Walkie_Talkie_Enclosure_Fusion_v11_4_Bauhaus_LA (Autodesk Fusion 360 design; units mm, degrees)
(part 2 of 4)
sketch "Restore Quiet Orb Status Aperture Sketch" plane through (0, 0, 0) normal (0, 0, 1) x axis (1, 0, 0)
  line L1 (0.05, -0.2) -> (-0.05, -0.2)
  line L2 (2.2, 8.05) -> (2.2, 1.95)
  line L3 (-0.05, 10.2) -> (0.05, 10.2)
  line L4 (-2.2, 1.95) -> (-2.2, 8.05)
  arc A1 centre (0.05, 1.95) radius 2.15 clockwise from (2.2, 1.95) to (0.05, -0.2)
  arc A2 centre (0.05, 8.05) radius 2.15 clockwise from (0.05, 10.2) to (2.2, 8.05)
  arc A3 centre (-0.05, 8.05) radius 2.15 clockwise from (-2.2, 8.05) to (-0.05, 10.2)
  arc A4 centre (-0.05, 1.95) radius 2.15 clockwise from (-0.05, -0.2) to (-2.2, 1.95)
extrude "Extrude33" cut sketch "Restore Quiet Orb Status Aperture Sketch" blind 3.2
sketch "Microphone Breakout Pocket Sketch" plane through (0, 0, 0) normal (0, 0, 1) x axis (1, 0, 0)
  line L1 (-6.4, -21.2) -> (-21.6, -21.2)
  line L2 (-4.9, -8.3) -> (-4.9, -19.7)
  line L3 (-21.6, -6.8) -> (-6.4, -6.8)
  line L4 (-23.1, -19.7) -> (-23.1, -8.3)
  line L5 (-6.55, -20.6) -> (-21.45, -20.6)
  line L6 (-5.5, -8.45) -> (-5.5, -19.55)
  line L7 (-21.45, -7.4) -> (-6.55, -7.4)
  line L8 (-22.5, -19.55) -> (-22.5, -8.45)
  arc A1 centre (-6.4, -19.7) radius 1.5 clockwise from (-4.9, -19.7) to (-6.4, -21.2)
  arc A2 centre (-6.4, -8.3) radius 1.5 clockwise from (-6.4, -6.8) to (-4.9, -8.3)
  arc A3 centre (-21.6, -8.3) radius 1.5 clockwise from (-23.1, -8.3) to (-21.6, -6.8)
  arc A4 centre (-21.6, -19.7) radius 1.5 clockwise from (-21.6, -21.2) to (-23.1, -19.7)
  arc A5 centre (-6.55, -19.55) radius 1.05 clockwise from (-5.5, -19.55) to (-6.55, -20.6)
  arc A6 centre (-6.55, -8.45) radius 1.05 clockwise from (-6.55, -7.4) to (-5.5, -8.45)
  arc A7 centre (-21.45, -8.45) radius 1.05 clockwise from (-22.5, -8.45) to (-21.45, -7.4)
  arc A8 centre (-21.45, -19.55) radius 1.05 clockwise from (-21.45, -20.6) to (-22.5, -19.55)
extrude "Extrude34" add sketch "Microphone Breakout Pocket Sketch" blind 3.2 from offset 2
sketch "Microphone Snap Lip Sketch" plane through (0, 0, 0) normal (0, 0, 1) x axis (1, 0, 0)
  line L1 (-12.5, -20.9) -> (-15.5, -20.9)
  line L2 (-12, -20.1) -> (-12, -20.4)
  line L3 (-15.5, -19.6) -> (-12.5, -19.6)
  line L4 (-16, -20.4) -> (-16, -20.1)
  arc A1 centre (-12.5, -20.4) radius 0.5 clockwise from (-12, -20.4) to (-12.5, -20.9)
  arc A2 centre (-12.5, -20.1) radius 0.5 clockwise from (-12.5, -19.6) to (-12, -20.1)
  arc A3 centre (-15.5, -20.1) radius 0.5 clockwise from (-16, -20.1) to (-15.5, -19.6)
  arc A4 centre (-15.5, -20.4) radius 0.5 clockwise from (-15.5, -20.9) to (-16, -20.4)
extrude "Extrude35" add sketch "Microphone Snap Lip Sketch" blind 0.4 from offset 4.95
sketch "Microphone Snap Lip Sketch (1)" plane through (0, 0, 0) normal (0, 0, 1) x axis (1, 0, 0)
  line L1 (-12.5, -8.4) -> (-15.5, -8.4)
  line L2 (-12, -7.6) -> (-12, -7.9)
  line L3 (-15.5, -7.1) -> (-12.5, -7.1)
  line L4 (-16, -7.9) -> (-16, -7.6)
  arc A1 centre (-12.5, -7.9) radius 0.5 clockwise from (-12, -7.9) to (-12.5, -8.4)
  arc A2 centre (-12.5, -7.6) radius 0.5 clockwise from (-12.5, -7.1) to (-12, -7.6)
  arc A3 centre (-15.5, -7.6) radius 0.5 clockwise from (-16, -7.6) to (-15.5, -7.1)
  arc A4 centre (-15.5, -7.9) radius 0.5 clockwise from (-15.5, -8.4) to (-16, -7.9)
extrude "Extrude36" add sketch "Microphone Snap Lip Sketch (1)" blind 0.4 from offset 4.95
sketch "Front Switch Clamp Boss Sketch" plane through (0, 0, 0) normal (0, 0, 1) x axis (1, 0, 0)
  circle C1 centre (-17, -47) radius 2.1
extrude "Extrude37" add sketch "Front Switch Clamp Boss Sketch" blind 8.85 from offset 2
sketch "Front Switch Clamp M2 Pilot Sketch" plane through (0, 0, 0) normal (0, 0, 1) x axis (1, 0, 0)
  circle C1 centre (-17, -47) radius 0.85
extrude "Extrude38" cut sketch "Front Switch Clamp M2 Pilot Sketch" blind 8.4 from offset 2.6
sketch "Front Switch Clamp Boss Sketch (1)" plane through (0, 0, 0) normal (0, 0, 1) x axis (1, 0, 0)
  circle C1 centre (17, -47) radius 2.1
extrude "Extrude39" add sketch "Front Switch Clamp Boss Sketch (1)" blind 8.85 from offset 2
sketch "Front Switch Clamp M2 Pilot Sketch (1)" plane through (0, 0, 0) normal (0, 0, 1) x axis (1, 0, 0)
  circle C1 centre (17, -47) radius 0.85
extrude "Extrude40" cut sketch "Front Switch Clamp M2 Pilot Sketch (1)" blind 8.4 from offset 2.6
sketch "Front Switch Body Reaction Bridge Sketch" plane through (0, 0, 0) normal (0, 0, 1) x axis (1, 0, 0)
  line L1 (16.5, -55) -> (-16.5, -55)
  line L2 (19.5, -42) -> (19.5, -52)
  line L3 (-16.5, -39) -> (16.5, -39)
  line L4 (-19.5, -52) -> (-19.5, -42)
  line L5 (2, -51) -> (-2, -51)
  line L6 (4, -45) -> (4, -49)
  line L7 (-2, -43) -> (2, -43)
  line L8 (-4, -49) -> (-4, -45)
  arc A1 centre (16.5, -52) radius 3 clockwise from (19.5, -52) to (16.5, -55)
  arc A2 centre (16.5, -42) radius 3 clockwise from (16.5, -39) to (19.5, -42)
  arc A3 centre (-16.5, -42) radius 3 clockwise from (-19.5, -42) to (-16.5, -39)
  arc A4 centre (-16.5, -52) radius 3 clockwise from (-16.5, -55) to (-19.5, -52)
  arc A5 centre (2, -49) radius 2 clockwise from (4, -49) to (2, -51)
  arc A6 centre (2, -45) radius 2 clockwise from (2, -43) to (4, -45)
  arc A7 centre (-2, -45) radius 2 clockwise from (-4, -45) to (-2, -43)
  arc A8 centre (-2, -49) radius 2 clockwise from (-2, -51) to (-4, -49)
extrude "Extrude41" add sketch "Front Switch Body Reaction Bridge Sketch" blind 0.2 from offset 3.2
sketch "PTT Interaction Field Sketch" plane through (0, 0, 0) normal (1, 0, 0) x axis (0, 0, -1)
  line L1 (-14.65, -17.5) -> (-14.85, -17.5)
  line L2 (-7.85, 34.7) -> (-7.85, -10.7)
  line L3 (-14.85, 41.5) -> (-14.65, 41.5)
  line L4 (-21.65, -10.7) -> (-21.65, 34.7)
  arc A1 centre (-14.65, -10.7) radius 6.8 clockwise from (-7.85, -10.7) to (-14.65, -17.5)
  arc A2 centre (-14.65, 34.7) radius 6.8 clockwise from (-14.65, 41.5) to (-7.85, 34.7)
  arc A3 centre (-14.85, 34.7) radius 6.8 clockwise from (-21.65, 34.7) to (-14.85, 41.5)
  arc A4 centre (-14.85, -10.7) radius 6.8 clockwise from (-14.85, -17.5) to (-21.65, -10.7)
extrude "Extrude42" cut sketch "PTT Interaction Field Sketch" blind -0.42 (= "-( 0.42 mm )") from offset 39.2
sketch "Unified Volume Interaction Field Sketch" plane through (0, 0, 0) normal (1, 0, 0) x axis (0, 0, -1)
  line L1 (-14.65, -21.25) -> (-14.85, -21.25)
  line L2 (-7.85, 31.45) -> (-7.85, -14.45)
  line L3 (-14.85, 38.25) -> (-14.65, 38.25)
  line L4 (-21.65, -14.45) -> (-21.65, 31.45)
  arc A1 centre (-14.65, -14.45) radius 6.8 clockwise from (-7.85, -14.45) to (-14.65, -21.25)
  arc A2 centre (-14.65, 31.45) radius 6.8 clockwise from (-14.65, 38.25) to (-7.85, 31.45)
  arc A3 centre (-14.85, 31.45) radius 6.8 clockwise from (-21.65, 31.45) to (-14.85, 38.25)
  arc A4 centre (-14.85, -14.45) radius 6.8 clockwise from (-14.85, -21.25) to (-21.65, -14.45)
extrude "Extrude43" cut sketch "Unified Volume Interaction Field Sketch" blind 0.42 from offset -39.2
sketch "Left PTT Through Opening Sketch" plane through (0, 0, 0) normal (1, 0, 0) x axis (0, 0, -1)
  line L1 (-14.65, -13.2) -> (-14.85, -13.2)
  line L2 (-10.25, 32.8) -> (-10.25, -8.8)
  line L3 (-14.85, 37.2) -> (-14.65, 37.2)
  line L4 (-19.25, -8.8) -> (-19.25, 32.8)
  arc A1 centre (-14.65, -8.8) radius 4.4 clockwise from (-10.25, -8.8) to (-14.65, -13.2)
  arc A2 centre (-14.65, 32.8) radius 4.4 clockwise from (-14.65, 37.2) to (-10.25, 32.8)
  arc A3 centre (-14.85, 32.8) radius 4.4 clockwise from (-19.25, 32.8) to (-14.85, 37.2)
  arc A4 centre (-14.85, -8.8) radius 4.4 clockwise from (-14.85, -13.2) to (-19.25, -8.8)
extrude "Extrude44" cut sketch "Left PTT Through Opening Sketch" blind 40
sketch "Volume Up Through Opening Sketch" plane through (0, 0, 0) normal (1, 0, 0) x axis (0, 0, -1)
  line L1 (-14.65, 15.15) -> (-14.85, 15.15)
  line L2 (-10.55, 26.75) -> (-10.55, 19.25)
  line L3 (-14.85, 30.85) -> (-14.65, 30.85)
  line L4 (-18.95, 19.25) -> (-18.95, 26.75)
  arc A1 centre (-14.65, 19.25) radius 4.1 clockwise from (-10.55, 19.25) to (-14.65, 15.15)
  arc A2 centre (-14.65, 26.75) radius 4.1 clockwise from (-14.65, 30.85) to (-10.55, 26.75)
  arc A3 centre (-14.85, 26.75) radius 4.1 clockwise from (-18.95, 26.75) to (-14.85, 30.85)
  arc A4 centre (-14.85, 19.25) radius 4.1 clockwise from (-14.85, 15.15) to (-18.95, 19.25)
extrude "Extrude45" cut sketch "Volume Up Through Opening Sketch" blind -40 (= "-( 40.00 mm )")
sketch "Volume Down Through Opening Sketch" plane through (0, 0, 0) normal (1, 0, 0) x axis (0, 0, -1)
  line L1 (-14.65, -13.85) -> (-14.85, -13.85)
  line L2 (-10.55, -2.25) -> (-10.55, -9.75)
  line L3 (-14.85, 1.85) -> (-14.65, 1.85)
  line L4 (-18.95, -9.75) -> (-18.95, -2.25)
  arc A1 centre (-14.65, -9.75) radius 4.1 clockwise from (-10.55, -9.75) to (-14.65, -13.85)
  arc A2 centre (-14.65, -2.25) radius 4.1 clockwise from (-14.65, 1.85) to (-10.55, -2.25)
  arc A3 centre (-14.85, -2.25) radius 4.1 clockwise from (-18.95, -2.25) to (-14.85, 1.85)
  arc A4 centre (-14.85, -9.75) radius 4.1 clockwise from (-14.85, -13.85) to (-18.95, -9.75)
extrude "Extrude46" cut sketch "Volume Down Through Opening Sketch" blind -40 (= "-( 40.00 mm )")
sketch "USB-C Full-Seating Local Wall Recess Sketch" plane through (0, 0, 0) normal (1, 0, 0) x axis (0, 0, -1)
  line L1 (-12.4264, -27.6393) -> (-12.9264, -27.6393)
  line L2 (-8.9764, -17.8393) -> (-8.9764, -24.1893)
  line L3 (-12.9264, -14.3893) -> (-12.4264, -14.3893)
  line L4 (-16.3764, -24.1893) -> (-16.3764, -17.8393)
  arc A1 centre (-12.4264, -24.1893) radius 3.45 clockwise from (-8.9764, -24.1893) to (-12.4264, -27.6393)
  arc A2 centre (-12.4264, -17.8393) radius 3.45 clockwise from (-12.4264, -14.3893) to (-8.9764, -17.8393)
  arc A3 centre (-12.9264, -17.8393) radius 3.45 clockwise from (-16.3764, -17.8393) to (-12.9264, -14.3893)
  arc A4 centre (-12.9264, -24.1893) radius 3.45 clockwise from (-12.9264, -27.6393) to (-16.3764, -24.1893)
extrude "Extrude47" cut sketch "USB-C Full-Seating Local Wall Recess Sketch" blind -2.9527 (= "-( 2.952733 mm )") from offset 39.2
sketch "Sketch48" plane through (0, 0, 0) normal (1, 0, 0) x axis (0, 0, -1)
  line L1 (-12.6264, -25.7043) -> (-12.7264, -25.7043)
  line L2 (-10.2799, -18.6708) -> (-10.2799, -23.3578)
  line L3 (-12.7264, -16.3243) -> (-12.6264, -16.3243)
  line L4 (-15.0729, -23.3578) -> (-15.0729, -18.6708)
  arc A1 centre (-12.6264, -23.3578) radius 2.3465 clockwise from (-10.2799, -23.3578) to (-12.6264, -25.7043)
  arc A2 centre (-12.6264, -18.6708) radius 2.3465 clockwise from (-12.6264, -16.3243) to (-10.2799, -18.6708)
  arc A3 centre (-12.7264, -18.6708) radius 2.3465 clockwise from (-15.0729, -18.6708) to (-12.7264, -16.3243)
  arc A4 centre (-12.7264, -23.3578) radius 2.3465 clockwise from (-12.7264, -25.7043) to (-15.0729, -23.3578)
extrude "Extrude48" cut sketch "Sketch48" blind 40
sketch "PTT Internal Switch Body Clearance Sketch" plane through (0, 0, 0) normal (1, 0, 0) x axis (0, 0, -1)
  line L1 (-10, 6.65) -> (-19.5, 6.65)
  line L2 (-9.55, 16.9) -> (-9.55, 7.1)
  line L3 (-19.5, 17.35) -> (-10, 17.35)
  line L4 (-19.95, 7.1) -> (-19.95, 16.9)
  arc A1 centre (-10, 7.1) radius 0.45 clockwise from (-9.55, 7.1) to (-10, 6.65)
  arc A2 centre (-10, 16.9) radius 0.45 clockwise from (-10, 17.35) to (-9.55, 16.9)
  arc A3 centre (-19.5, 16.9) radius 0.45 clockwise from (-19.95, 16.9) to (-19.5, 17.35)
  arc A4 centre (-19.5, 7.1) radius 0.45 clockwise from (-19.5, 6.65) to (-19.95, 7.1)
extrude "Extrude49" cut sketch "PTT Internal Switch Body Clearance Sketch" blind 5.1 from offset 31.9
sketch "PTT Switch Cage Anchor Sketch" plane through (0, 0, 0) normal (0, 0, 1) x axis (1, 0, 0)
  line L1 (32, 6.45) -> (31.5, 6.45)
  line L2 (32.35, 7.3) -> (32.35, 6.8)
  line L3 (31.5, 7.65) -> (32, 7.65)
  line L4 (31.15, 6.8) -> (31.15, 7.3)
  arc A1 centre (32, 6.8) radius 0.35 clockwise from (32.35, 6.8) to (32, 6.45)
  arc A2 centre (32, 7.3) radius 0.35 clockwise from (32, 7.65) to (32.35, 7.3)
  arc A3 centre (31.5, 7.3) radius 0.35 clockwise from (31.15, 7.3) to (31.5, 7.65)
  arc A4 centre (31.5, 6.8) radius 0.35 clockwise from (31.5, 6.45) to (31.15, 6.8)
extrude "Extrude50" add sketch "PTT Switch Cage Anchor Sketch" blind 7.35 from offset 2
sketch "PTT Switch Cage Anchor Sketch (1)" plane through (0, 0, 0) normal (0, 0, 1) x axis (1, 0, 0)
  line L1 (32, 16.35) -> (31.5, 16.35)
  line L2 (32.35, 17.2) -> (32.35, 16.7)
  line L3 (31.5, 17.55) -> (32, 17.55)
  line L4 (31.15, 16.7) -> (31.15, 17.2)
  arc A1 centre (32, 16.7) radius 0.35 clockwise from (32.35, 16.7) to (32, 16.35)
  arc A2 centre (32, 17.2) radius 0.35 clockwise from (32, 17.55) to (32.35, 17.2)
  arc A3 centre (31.5, 17.2) radius 0.35 clockwise from (31.15, 17.2) to (31.5, 17.55)
  arc A4 centre (31.5, 16.7) radius 0.35 clockwise from (31.5, 16.35) to (31.15, 16.7)
extrude "Extrude51" add sketch "PTT Switch Cage Anchor Sketch (1)" blind 7.35 from offset 2
sketch "PTT Switch Floor Sketch" plane through (0, 0, 0) normal (0, 0, 1) x axis (1, 0, 0)
  line L1 (36.45, 6.65) -> (31.75, 6.65)
  line L2 (36.9, 16.9) -> (36.9, 7.1)
  line L3 (31.75, 17.35) -> (36.45, 17.35)
  line L4 (31.3, 7.1) -> (31.3, 16.9)
  arc A1 centre (36.45, 7.1) radius 0.45 clockwise from (36.9, 7.1) to (36.45, 6.65)
  arc A2 centre (36.45, 16.9) radius 0.45 clockwise from (36.45, 17.35) to (36.9, 16.9)
  arc A3 centre (31.75, 16.9) radius 0.45 clockwise from (31.3, 16.9) to (31.75, 17.35)
  arc A4 centre (31.75, 7.1) radius 0.45 clockwise from (31.75, 6.65) to (31.3, 7.1)
extrude "Extrude52" add sketch "PTT Switch Floor Sketch" blind 0.55 from offset 9.25
sketch "PTT Switch Inward Backstop Sketch" plane through (0, 0, 0) normal (0, 0, 1) x axis (1, 0, 0)
  line L1 (31.85, 6.65) -> (31.65, 6.65)
  line L2 (32.2, 17) -> (32.2, 7)
  line L3 (31.65, 17.35) -> (31.85, 17.35)
  line L4 (31.3, 7) -> (31.3, 17)
  arc A1 centre (31.85, 7) radius 0.35 clockwise from (32.2, 7) to (31.85, 6.65)
  arc A2 centre (31.85, 17) radius 0.35 clockwise from (31.85, 17.35) to (32.2, 17)
  arc A3 centre (31.65, 17) radius 0.35 clockwise from (31.3, 17) to (31.65, 17.35)
  arc A4 centre (31.65, 7) radius 0.35 clockwise from (31.65, 6.65) to (31.3, 7)
extrude "Extrude53" add sketch "PTT Switch Inward Backstop Sketch" blind 5.75 from offset 9.25
sketch "PTT Switch Side Rail Sketch" plane through (0, 0, 0) normal (0, 0, 1) x axis (1, 0, 0)
  line L1 (36.675, 6.65) -> (32.325, 6.65)
  line L2 (36.975, 7.15) -> (36.975, 6.95)
  line L3 (32.325, 7.45) -> (36.675, 7.45)
  line L4 (32.025, 6.95) -> (32.025, 7.15)
  arc A1 centre (36.675, 6.95) radius 0.3 clockwise from (36.975, 6.95) to (36.675, 6.65)
  arc A2 centre (36.675, 7.15) radius 0.3 clockwise from (36.675, 7.45) to (36.975, 7.15)
  arc A3 centre (32.325, 7.15) radius 0.3 clockwise from (32.025, 7.15) to (32.325, 7.45)
  arc A4 centre (32.325, 6.95) radius 0.3 clockwise from (32.325, 6.65) to (32.025, 6.95)
extrude "Extrude54" add sketch "PTT Switch Side Rail Sketch" blind 5.75 from offset 9.25
sketch "PTT Switch Side Rail Sketch (1)" plane through (0, 0, 0) normal (0, 0, 1) x axis (1, 0, 0)
  line L1 (36.675, 16.55) -> (32.325, 16.55)
  line L2 (36.975, 17.05) -> (36.975, 16.85)
  line L3 (32.325, 17.35) -> (36.675, 17.35)
  line L4 (32.025, 16.85) -> (32.025, 17.05)
  arc A1 centre (36.675, 16.85) radius 0.3 clockwise from (36.975, 16.85) to (36.675, 16.55)
  arc A2 centre (36.675, 17.05) radius 0.3 clockwise from (36.675, 17.35) to (36.975, 17.05)
  arc A3 centre (32.325, 17.05) radius 0.3 clockwise from (32.025, 17.05) to (32.325, 17.35)
  arc A4 centre (32.325, 16.85) radius 0.3 clockwise from (32.325, 16.55) to (32.025, 16.85)
extrude "Extrude55" add sketch "PTT Switch Side Rail Sketch (1)" blind 5.75 from offset 9.25
sketch "PTT Switch Actuator Shoulder Sketch" plane through (0, 0, 0) normal (0, 0, 1) x axis (1, 0, 0)
  line L1 (37.28, 6.65) -> (37.22, 6.65)
  line L2 (37.5, 17.13) -> (37.5, 6.87)
  line L3 (37.22, 17.35) -> (37.28, 17.35)
  line L4 (37, 6.87) -> (37, 17.13)
  arc A1 centre (37.28, 6.87) radius 0.22 clockwise from (37.5, 6.87) to (37.28, 6.65)
  arc A2 centre (37.28, 17.13) radius 0.22 clockwise from (37.28, 17.35) to (37.5, 17.13)
  arc A3 centre (37.22, 17.13) radius 0.22 clockwise from (37, 17.13) to (37.22, 17.35)
  arc A4 centre (37.22, 6.87) radius 0.22 clockwise from (37.22, 6.65) to (37, 6.87)
extrude "Extrude56" add sketch "PTT Switch Actuator Shoulder Sketch" blind 5.75 from offset 9.25
sketch "PTT Actuator Passage Sketch" plane through (0, 0, 0) normal (1, 0, 0) x axis (0, 0, -1)
  line L1 (-15.9, 10.6) -> (-17.5, 10.6)
  line L2 (-15.3, 12.8) -> (-15.3, 11.2)
  line L3 (-17.5, 13.4) -> (-15.9, 13.4)
  line L4 (-18.1, 11.2) -> (-18.1, 12.8)
  arc A1 centre (-15.9, 11.2) radius 0.6 clockwise from (-15.3, 11.2) to (-15.9, 10.6)
  arc A2 centre (-15.9, 12.8) radius 0.6 clockwise from (-15.9, 13.4) to (-15.3, 12.8)
  arc A3 centre (-17.5, 12.8) radius 0.6 clockwise from (-18.1, 12.8) to (-17.5, 13.4)
  arc A4 centre (-17.5, 11.2) radius 0.6 clockwise from (-17.5, 10.6) to (-18.1, 11.2)
extrude "Extrude57" cut sketch "PTT Actuator Passage Sketch" blind 1.9 from offset 35.8
sketch "Volume Up Internal Switch Body Clearance Sketch" plane through (0, 0, 0) normal (1, 0, 0) x axis (0, 0, -1)
  line L1 (-10, 17.65) -> (-19.5, 17.65)
  line L2 (-9.55, 27.9) -> (-9.55, 18.1)
  line L3 (-19.5, 28.35) -> (-10, 28.35)
  line L4 (-19.95, 18.1) -> (-19.95, 27.9)
  arc A1 centre (-10, 18.1) radius 0.45 clockwise from (-9.55, 18.1) to (-10, 17.65)
  arc A2 centre (-10, 27.9) radius 0.45 clockwise from (-10, 28.35) to (-9.55, 27.9)
  arc A3 centre (-19.5, 27.9) radius 0.45 clockwise from (-19.95, 27.9) to (-19.5, 28.35)
  arc A4 centre (-19.5, 18.1) radius 0.45 clockwise from (-19.5, 17.65) to (-19.95, 18.1)
extrude "Extrude58" cut sketch "Volume Up Internal Switch Body Clearance Sketch" blind -5.1 (= "-( 5.10 mm )") from offset -31.9
sketch "Volume Up Switch Cage Anchor Sketch" plane through (0, 0, 0) normal (0, 0, 1) x axis (1, 0, 0)
  line L1 (-31.5, 17.45) -> (-32, 17.45)
  line L2 (-31.15, 18.3) -> (-31.15, 17.8)
  line L3 (-32, 18.65) -> (-31.5, 18.65)
  line L4 (-32.35, 17.8) -> (-32.35, 18.3)
  arc A1 centre (-31.5, 17.8) radius 0.35 clockwise from (-31.15, 17.8) to (-31.5, 17.45)
  arc A2 centre (-31.5, 18.3) radius 0.35 clockwise from (-31.5, 18.65) to (-31.15, 18.3)
  arc A3 centre (-32, 18.3) radius 0.35 clockwise from (-32.35, 18.3) to (-32, 18.65)
  arc A4 centre (-32, 17.8) radius 0.35 clockwise from (-32, 17.45) to (-32.35, 17.8)
extrude "Extrude59" add sketch "Volume Up Switch Cage Anchor Sketch" blind 7.35 from offset 2
sketch "Volume Up Switch Cage Anchor Sketch (1)" plane through (0, 0, 0) normal (0, 0, 1) x axis (1, 0, 0)
  line L1 (-31.5, 27.35) -> (-32, 27.35)
  line L2 (-31.15, 28.2) -> (-31.15, 27.7)
  line L3 (-32, 28.55) -> (-31.5, 28.55)
  line L4 (-32.35, 27.7) -> (-32.35, 28.2)
  arc A1 centre (-31.5, 27.7) radius 0.35 clockwise from (-31.15, 27.7) to (-31.5, 27.35)
  arc A2 centre (-31.5, 28.2) radius 0.35 clockwise from (-31.5, 28.55) to (-31.15, 28.2)
  arc A3 centre (-32, 28.2) radius 0.35 clockwise from (-32.35, 28.2) to (-32, 28.55)
  arc A4 centre (-32, 27.7) radius 0.35 clockwise from (-32, 27.35) to (-32.35, 27.7)
extrude "Extrude60" add sketch "Volume Up Switch Cage Anchor Sketch (1)" blind 7.35 from offset 2
sketch "Volume Up Switch Floor Sketch" plane through (0, 0, 0) normal (0, 0, 1) x axis (1, 0, 0)
  line L1 (-31.75, 17.65) -> (-36.45, 17.65)
  line L2 (-31.3, 27.9) -> (-31.3, 18.1)
  line L3 (-36.45, 28.35) -> (-31.75, 28.35)
  line L4 (-36.9, 18.1) -> (-36.9, 27.9)
  arc A1 centre (-31.75, 18.1) radius 0.45 clockwise from (-31.3, 18.1) to (-31.75, 17.65)
  arc A2 centre (-31.75, 27.9) radius 0.45 clockwise from (-31.75, 28.35) to (-31.3, 27.9)
  arc A3 centre (-36.45, 27.9) radius 0.45 clockwise from (-36.9, 27.9) to (-36.45, 28.35)
  arc A4 centre (-36.45, 18.1) radius 0.45 clockwise from (-36.45, 17.65) to (-36.9, 18.1)
extrude "Extrude61" add sketch "Volume Up Switch Floor Sketch" blind 0.55 from offset 9.25
sketch "Volume Up Switch Inward Backstop Sketch" plane through (0, 0, 0) normal (0, 0, 1) x axis (1, 0, 0)
  line L1 (-31.65, 17.65) -> (-31.85, 17.65)
  line L2 (-31.3, 28) -> (-31.3, 18)
  line L3 (-31.85, 28.35) -> (-31.65, 28.35)
  line L4 (-32.2, 18) -> (-32.2, 28)
  arc A1 centre (-31.65, 18) radius 0.35 clockwise from (-31.3, 18) to (-31.65, 17.65)
  arc A2 centre (-31.65, 28) radius 0.35 clockwise from (-31.65, 28.35) to (-31.3, 28)
  arc A3 centre (-31.85, 28) radius 0.35 clockwise from (-32.2, 28) to (-31.85, 28.35)
  arc A4 centre (-31.85, 18) radius 0.35 clockwise from (-31.85, 17.65) to (-32.2, 18)
extrude "Extrude62" add sketch "Volume Up Switch Inward Backstop Sketch" blind 5.75 from offset 9.25
sketch "Volume Up Switch Side Rail Sketch" plane through (0, 0, 0) normal (0, 0, 1) x axis (1, 0, 0)
  line L1 (-32.325, 17.65) -> (-36.675, 17.65)
  line L2 (-32.025, 18.15) -> (-32.025, 17.95)
  line L3 (-36.675, 18.45) -> (-32.325, 18.45)
  line L4 (-36.975, 17.95) -> (-36.975, 18.15)
  arc A1 centre (-32.325, 17.95) radius 0.3 clockwise from (-32.025, 17.95) to (-32.325, 17.65)
  arc A2 centre (-32.325, 18.15) radius 0.3 clockwise from (-32.325, 18.45) to (-32.025, 18.15)
  arc A3 centre (-36.675, 18.15) radius 0.3 clockwise from (-36.975, 18.15) to (-36.675, 18.45)
  arc A4 centre (-36.675, 17.95) radius 0.3 clockwise from (-36.675, 17.65) to (-36.975, 17.95)
extrude "Extrude63" add sketch "Volume Up Switch Side Rail Sketch" blind 5.75 from offset 9.25
sketch "Volume Up Switch Side Rail Sketch (1)" plane through (0, 0, 0) normal (0, 0, 1) x axis (1, 0, 0)
  line L1 (-32.325, 27.55) -> (-36.675, 27.55)
  line L2 (-32.025, 28.05) -> (-32.025, 27.85)
  line L3 (-36.675, 28.35) -> (-32.325, 28.35)
  line L4 (-36.975, 27.85) -> (-36.975, 28.05)
  arc A1 centre (-32.325, 27.85) radius 0.3 clockwise from (-32.025, 27.85) to (-32.325, 27.55)
  arc A2 centre (-32.325, 28.05) radius 0.3 clockwise from (-32.325, 28.35) to (-32.025, 28.05)
  arc A3 centre (-36.675, 28.05) radius 0.3 clockwise from (-36.975, 28.05) to (-36.675, 28.35)
  arc A4 centre (-36.675, 27.85) radius 0.3 clockwise from (-36.675, 27.55) to (-36.975, 27.85)
extrude "Extrude64" add sketch "Volume Up Switch Side Rail Sketch (1)" blind 5.75 from offset 9.25
sketch "Volume Up Switch Actuator Shoulder Sketch" plane through (0, 0, 0) normal (0, 0, 1) x axis (1, 0, 0)
  line L1 (-37.22, 17.65) -> (-37.28, 17.65)
  line L2 (-37, 28.13) -> (-37, 17.87)
  line L3 (-37.28, 28.35) -> (-37.22, 28.35)
  line L4 (-37.5, 17.87) -> (-37.5, 28.13)
  arc A1 centre (-37.22, 17.87) radius 0.22 clockwise from (-37, 17.87) to (-37.22, 17.65)
  arc A2 centre (-37.22, 28.13) radius 0.22 clockwise from (-37.22, 28.35) to (-37, 28.13)
  arc A3 centre (-37.28, 28.13) radius 0.22 clockwise from (-37.5, 28.13) to (-37.28, 28.35)
  arc A4 centre (-37.28, 17.87) radius 0.22 clockwise from (-37.28, 17.65) to (-37.5, 17.87)
extrude "Extrude65" add sketch "Volume Up Switch Actuator Shoulder Sketch" blind 5.75 from offset 9.25
sketch "Volume Up Actuator Passage Sketch" plane through (0, 0, 0) normal (1, 0, 0) x axis (0, 0, -1)
  line L1 (-15.9, 21.6) -> (-17.5, 21.6)
  line L2 (-15.3, 23.8) -> (-15.3, 22.2)
  line L3 (-17.5, 24.4) -> (-15.9, 24.4)
  line L4 (-18.1, 22.2) -> (-18.1, 23.8)
  arc A1 centre (-15.9, 22.2) radius 0.6 clockwise from (-15.3, 22.2) to (-15.9, 21.6)
  arc A2 centre (-15.9, 23.8) radius 0.6 clockwise from (-15.9, 24.4) to (-15.3, 23.8)
  arc A3 centre (-17.5, 23.8) radius 0.6 clockwise from (-18.1, 23.8) to (-17.5, 24.4)
  arc A4 centre (-17.5, 22.2) radius 0.6 clockwise from (-17.5, 21.6) to (-18.1, 22.2)
extrude "Extrude66" cut sketch "Volume Up Actuator Passage Sketch" blind -1.9 (= "-( 1.90 mm )") from offset -35.8
sketch "Volume Down Internal Switch Body Clearance Sketch" plane through (0, 0, 0) normal (1, 0, 0) x axis (0, 0, -1)
  line L1 (-10, -11.35) -> (-19.5, -11.35)
  line L2 (-9.55, -1.1) -> (-9.55, -10.9)
  line L3 (-19.5, -0.65) -> (-10, -0.65)
  line L4 (-19.95, -10.9) -> (-19.95, -1.1)
  arc A1 centre (-10, -10.9) radius 0.45 clockwise from (-9.55, -10.9) to (-10, -11.35)
  arc A2 centre (-10, -1.1) radius 0.45 clockwise from (-10, -0.65) to (-9.55, -1.1)
  arc A3 centre (-19.5, -1.1) radius 0.45 clockwise from (-19.95, -1.1) to (-19.5, -0.65)
  arc A4 centre (-19.5, -10.9) radius 0.45 clockwise from (-19.5, -11.35) to (-19.95, -10.9)
extrude "Extrude67" cut sketch "Volume Down Internal Switch Body Clearance Sketch" blind -5.1 (= "-( 5.10 mm )") from offset -31.9
sketch "Volume Down Switch Cage Anchor Sketch" plane through (0, 0, 0) normal (0, 0, 1) x axis (1, 0, 0)
  line L1 (-31.5, -11.55) -> (-32, -11.55)
  line L2 (-31.15, -10.7) -> (-31.15, -11.2)
  line L3 (-32, -10.35) -> (-31.5, -10.35)
  line L4 (-32.35, -11.2) -> (-32.35, -10.7)
  arc A1 centre (-31.5, -11.2) radius 0.35 clockwise from (-31.15, -11.2) to (-31.5, -11.55)
  arc A2 centre (-31.5, -10.7) radius 0.35 clockwise from (-31.5, -10.35) to (-31.15, -10.7)
  arc A3 centre (-32, -10.7) radius 0.35 clockwise from (-32.35, -10.7) to (-32, -10.35)
  arc A4 centre (-32, -11.2) radius 0.35 clockwise from (-32, -11.55) to (-32.35, -11.2)
extrude "Extrude68" add sketch "Volume Down Switch Cage Anchor Sketch" blind 7.35 from offset 2
sketch "Volume Down Switch Cage Anchor Sketch (1)" plane through (0, 0, 0) normal (0, 0, 1) x axis (1, 0, 0)
  line L1 (-31.5, -1.65) -> (-32, -1.65)
  line L2 (-31.15, -0.8) -> (-31.15, -1.3)
  line L3 (-32, -0.45) -> (-31.5, -0.45)
  line L4 (-32.35, -1.3) -> (-32.35, -0.8)
  arc A1 centre (-31.5, -1.3) radius 0.35 clockwise from (-31.15, -1.3) to (-31.5, -1.65)
  arc A2 centre (-31.5, -0.8) radius 0.35 clockwise from (-31.5, -0.45) to (-31.15, -0.8)
  arc A3 centre (-32, -0.8) radius 0.35 clockwise from (-32.35, -0.8) to (-32, -0.45)
  arc A4 centre (-32, -1.3) radius 0.35 clockwise from (-32, -1.65) to (-32.35, -1.3)
extrude "Extrude69" add sketch "Volume Down Switch Cage Anchor Sketch (1)" blind 7.35 from offset 2
sketch "Volume Down Switch Floor Sketch" plane through (0, 0, 0) normal (0, 0, 1) x axis (1, 0, 0)
  line L1 (-31.75, -11.35) -> (-36.45, -11.35)
  line L2 (-31.3, -1.1) -> (-31.3, -10.9)
  line L3 (-36.45, -0.65) -> (-31.75, -0.65)
  line L4 (-36.9, -10.9) -> (-36.9, -1.1)
  arc A1 centre (-31.75, -10.9) radius 0.45 clockwise from (-31.3, -10.9) to (-31.75, -11.35)
  arc A2 centre (-31.75, -1.1) radius 0.45 clockwise from (-31.75, -0.65) to (-31.3, -1.1)
  arc A3 centre (-36.45, -1.1) radius 0.45 clockwise from (-36.9, -1.1) to (-36.45, -0.65)
  arc A4 centre (-36.45, -10.9) radius 0.45 clockwise from (-36.45, -11.35) to (-36.9, -10.9)
extrude "Extrude70" add sketch "Volume Down Switch Floor Sketch" blind 0.55 from offset 9.25
sketch "Volume Down Switch Inward Backstop Sketch" plane through (0, 0, 0) normal (0, 0, 1) x axis (1, 0, 0)
  line L1 (-31.65, -11.35) -> (-31.85, -11.35)
  line L2 (-31.3, -1) -> (-31.3, -11)
  line L3 (-31.85, -0.65) -> (-31.65, -0.65)
  line L4 (-32.2, -11) -> (-32.2, -1)
  arc A1 centre (-31.65, -11) radius 0.35 clockwise from (-31.3, -11) to (-31.65, -11.35)
  arc A2 centre (-31.65, -1) radius 0.35 clockwise from (-31.65, -0.65) to (-31.3, -1)
  arc A3 centre (-31.85, -1) radius 0.35 clockwise from (-32.2, -1) to (-31.85, -0.65)
  arc A4 centre (-31.85, -11) radius 0.35 clockwise from (-31.85, -11.35) to (-32.2, -11)
extrude "Extrude71" add sketch "Volume Down Switch Inward Backstop Sketch" blind 5.75 from offset 9.25
sketch "Volume Down Switch Side Rail Sketch" plane through (0, 0, 0) normal (0, 0, 1) x axis (1, 0, 0)
  line L1 (-32.325, -11.35) -> (-36.675, -11.35)
  line L2 (-32.025, -10.85) -> (-32.025, -11.05)
  line L3 (-36.675, -10.55) -> (-32.325, -10.55)
  line L4 (-36.975, -11.05) -> (-36.975, -10.85)
  arc A1 centre (-32.325, -11.05) radius 0.3 clockwise from (-32.025, -11.05) to (-32.325, -11.35)
  arc A2 centre (-32.325, -10.85) radius 0.3 clockwise from (-32.325, -10.55) to (-32.025, -10.85)
  arc A3 centre (-36.675, -10.85) radius 0.3 clockwise from (-36.975, -10.85) to (-36.675, -10.55)
  arc A4 centre (-36.675, -11.05) radius 0.3 clockwise from (-36.675, -11.35) to (-36.975, -11.05)
extrude "Extrude72" add sketch "Volume Down Switch Side Rail Sketch" blind 5.75 from offset 9.25
sketch "Volume Down Switch Side Rail Sketch (1)" plane through (0, 0, 0) normal (0, 0, 1) x axis (1, 0, 0)
  line L1 (-32.325, -1.45) -> (-36.675, -1.45)
  line L2 (-32.025, -0.95) -> (-32.025, -1.15)
  line L3 (-36.675, -0.65) -> (-32.325, -0.65)
  line L4 (-36.975, -1.15) -> (-36.975, -0.95)
  arc A1 centre (-32.325, -1.15) radius 0.3 clockwise from (-32.025, -1.15) to (-32.325, -1.45)
  arc A2 centre (-32.325, -0.95) radius 0.3 clockwise from (-32.325, -0.65) to (-32.025, -0.95)
  arc A3 centre (-36.675, -0.95) radius 0.3 clockwise from (-36.975, -0.95) to (-36.675, -0.65)
  arc A4 centre (-36.675, -1.15) radius 0.3 clockwise from (-36.675, -1.45) to (-36.975, -1.15)
extrude "Extrude73" add sketch "Volume Down Switch Side Rail Sketch (1)" blind 5.75 from offset 9.25
sketch "Volume Down Switch Actuator Shoulder Sketch" plane through (0, 0, 0) normal (0, 0, 1) x axis (1, 0, 0)
  line L1 (-37.22, -11.35) -> (-37.28, -11.35)
  line L2 (-37, -0.87) -> (-37, -11.13)
  line L3 (-37.28, -0.65) -> (-37.22, -0.65)
  line L4 (-37.5, -11.13) -> (-37.5, -0.87)
  arc A1 centre (-37.22, -11.13) radius 0.22 clockwise from (-37, -11.13) to (-37.22, -11.35)
  arc A2 centre (-37.22, -0.87) radius 0.22 clockwise from (-37.22, -0.65) to (-37, -0.87)
  arc A3 centre (-37.28, -0.87) radius 0.22 clockwise from (-37.5, -0.87) to (-37.28, -0.65)
  arc A4 centre (-37.28, -11.13) radius 0.22 clockwise from (-37.28, -11.35) to (-37.5, -11.13)
extrude "Extrude74" add sketch "Volume Down Switch Actuator Shoulder Sketch" blind 5.75 from offset 9.25
sketch "Volume Down Actuator Passage Sketch" plane through (0, 0, 0) normal (1, 0, 0) x axis (0, 0, -1)
  line L1 (-15.9, -7.4) -> (-17.5, -7.4)
  line L2 (-15.3, -5.2) -> (-15.3, -6.8)
  line L3 (-17.5, -4.6) -> (-15.9, -4.6)
  line L4 (-18.1, -6.8) -> (-18.1, -5.2)
  arc A1 centre (-15.9, -6.8) radius 0.6 clockwise from (-15.3, -6.8) to (-15.9, -7.4)
  arc A2 centre (-15.9, -5.2) radius 0.6 clockwise from (-15.9, -4.6) to (-15.3, -5.2)
  arc A3 centre (-17.5, -5.2) radius 0.6 clockwise from (-18.1, -5.2) to (-17.5, -4.6)
  arc A4 centre (-17.5, -6.8) radius 0.6 clockwise from (-17.5, -7.4) to (-18.1, -6.8)
extrude "Extrude75" cut sketch "Volume Down Actuator Passage Sketch" blind -1.9 (= "-( 1.90 mm )") from offset -35.8
sketch "PCB Front Substrate Ledge Sketch" plane through (0, 0, 0) normal (0, 0, 1) x axis (1, 0, 0)
  line L1 (-27.8, -25) -> (-36.2, -25)
  line L2 (-27, -19.8) -> (-27, -24.2)
  line L3 (-36.2, -19) -> (-27.8, -19)
  line L4 (-37, -24.2) -> (-37, -19.8)
  arc A1 centre (-27.8, -24.2) radius 0.8 clockwise from (-27, -24.2) to (-27.8, -25)
  arc A2 centre (-27.8, -19.8) radius 0.8 clockwise from (-27.8, -19) to (-27, -19.8)
  arc A3 centre (-36.2, -19.8) radius 0.8 clockwise from (-37, -19.8) to (-36.2, -19)
  arc A4 centre (-36.2, -24.2) radius 0.8 clockwise from (-36.2, -25) to (-37, -24.2)
extrude "Extrude76" add sketch "PCB Front Substrate Ledge Sketch" blind 2.34 from offset 7.6
sketch "PCB Front Substrate Ledge Sketch (1)" plane through (0, 0, 0) normal (0, 0, 1) x axis (1, 0, 0)
  line L1 (-27.8, 31) -> (-36.2, 31)
  line L2 (-27, 36.2) -> (-27, 31.8)
  line L3 (-36.2, 37) -> (-27.8, 37)
  line L4 (-37, 31.8) -> (-37, 36.2)
  arc A1 centre (-27.8, 31.8) radius 0.8 clockwise from (-27, 31.8) to (-27.8, 31)
  arc A2 centre (-27.8, 36.2) radius 0.8 clockwise from (-27.8, 37) to (-27, 36.2)
  arc A3 centre (-36.2, 36.2) radius 0.8 clockwise from (-37, 36.2) to (-36.2, 37)
  arc A4 centre (-36.2, 31.8) radius 0.8 clockwise from (-36.2, 31) to (-37, 31.8)
extrude "Extrude77" add sketch "PCB Front Substrate Ledge Sketch (1)" blind 2.34 from offset 7.6
sketch "PCB Front Substrate Ledge Sketch (2)" plane through (0, 0, 0) normal (0, 0, 1) x axis (1, 0, 0)
  line L1 (36.2, -25) -> (27.8, -25)
  line L2 (37, -19.8) -> (37, -24.2)
  line L3 (27.8, -19) -> (36.2, -19)
  line L4 (27, -24.2) -> (27, -19.8)
  arc A1 centre (36.2, -24.2) radius 0.8 clockwise from (37, -24.2) to (36.2, -25)
  arc A2 centre (36.2, -19.8) radius 0.8 clockwise from (36.2, -19) to (37, -19.8)
  arc A3 centre (27.8, -19.8) radius 0.8 clockwise from (27, -19.8) to (27.8, -19)
  arc A4 centre (27.8, -24.2) radius 0.8 clockwise from (27.8, -25) to (27, -24.2)
extrude "Extrude78" add sketch "PCB Front Substrate Ledge Sketch (2)" blind 2.34 from offset 7.6
sketch "PCB Front Substrate Ledge Sketch (3)" plane through (0, 0, 0) normal (0, 0, 1) x axis (1, 0, 0)
  line L1 (36.2, 31) -> (27.8, 31)
  line L2 (37, 36.2) -> (37, 31.8)
  line L3 (27.8, 37) -> (36.2, 37)
  line L4 (27, 31.8) -> (27, 36.2)
  arc A1 centre (36.2, 31.8) radius 0.8 clockwise from (37, 31.8) to (36.2, 31)
  arc A2 centre (36.2, 36.2) radius 0.8 clockwise from (36.2, 37) to (37, 36.2)
  arc A3 centre (27.8, 36.2) radius 0.8 clockwise from (27, 36.2) to (27.8, 37)
  arc A4 centre (27.8, 31.8) radius 0.8 clockwise from (27.8, 31) to (27, 31.8)
extrude "Extrude79" add sketch "PCB Front Substrate Ledge Sketch (3)" blind 2.34 from offset 7.6
sketch "PCB X Edge Locator Sketch" plane through (0, 0, 0) normal (0, 0, 1) x axis (1, 0, 0)
  line L1 (-30.71, -25.5) -> (-31.21, -25.5)
  line L2 (-30.26, -18.95) -> (-30.26, -25.05)
  line L3 (-31.21, -18.5) -> (-30.71, -18.5)
  line L4 (-31.66, -25.05) -> (-31.66, -18.95)
  arc A1 centre (-30.71, -25.05) radius 0.45 clockwise from (-30.26, -25.05) to (-30.71, -25.5)
  arc A2 centre (-30.71, -18.95) radius 0.45 clockwise from (-30.71, -18.5) to (-30.26, -18.95)
  arc A3 centre (-31.21, -18.95) radius 0.45 clockwise from (-31.66, -18.95) to (-31.21, -18.5)
  arc A4 centre (-31.21, -25.05) radius 0.45 clockwise from (-31.21, -25.5) to (-31.66, -25.05)
extrude "Extrude80" add sketch "PCB X Edge Locator Sketch" blind 2 from offset 9.74
sketch "PCB X Edge Locator Sketch (1)" plane through (0, 0, 0) normal (0, 0, 1) x axis (1, 0, 0)
  line L1 (-30.71, 30.5) -> (-31.21, 30.5)
  line L2 (-30.26, 37.05) -> (-30.26, 30.95)
  line L3 (-31.21, 37.5) -> (-30.71, 37.5)
  line L4 (-31.66, 30.95) -> (-31.66, 37.05)
  arc A1 centre (-30.71, 30.95) radius 0.45 clockwise from (-30.26, 30.95) to (-30.71, 30.5)
  arc A2 centre (-30.71, 37.05) radius 0.45 clockwise from (-30.71, 37.5) to (-30.26, 37.05)
  arc A3 centre (-31.21, 37.05) radius 0.45 clockwise from (-31.66, 37.05) to (-31.21, 37.5)
  arc A4 centre (-31.21, 30.95) radius 0.45 clockwise from (-31.21, 30.5) to (-31.66, 30.95)
extrude "Extrude81" add sketch "PCB X Edge Locator Sketch (1)" blind 2 from offset 9.74
sketch "PCB X Edge Locator Sketch (2)" plane through (0, 0, 0) normal (0, 0, 1) x axis (1, 0, 0)
  line L1 (31.21, -25.5) -> (30.71, -25.5)
  line L2 (31.66, -18.95) -> (31.66, -25.05)
  line L3 (30.71, -18.5) -> (31.21, -18.5)
  line L4 (30.26, -25.05) -> (30.26, -18.95)
  arc A1 centre (31.21, -25.05) radius 0.45 clockwise from (31.66, -25.05) to (31.21, -25.5)
  arc A2 centre (31.21, -18.95) radius 0.45 clockwise from (31.21, -18.5) to (31.66, -18.95)
  arc A3 centre (30.71, -18.95) radius 0.45 clockwise from (30.26, -18.95) to (30.71, -18.5)
  arc A4 centre (30.71, -25.05) radius 0.45 clockwise from (30.71, -25.5) to (30.26, -25.05)
extrude "Extrude82" add sketch "PCB X Edge Locator Sketch (2)" blind 2 from offset 9.74
sketch "PCB X Edge Locator Sketch (3)" plane through (0, 0, 0) normal (0, 0, 1) x axis (1, 0, 0)
  line L1 (31.21, 30.5) -> (30.71, 30.5)
  line L2 (31.66, 37.05) -> (31.66, 30.95)
  line L3 (30.71, 37.5) -> (31.21, 37.5)
  line L4 (30.26, 30.95) -> (30.26, 37.05)
  arc A1 centre (31.21, 30.95) radius 0.45 clockwise from (31.66, 30.95) to (31.21, 30.5)
  arc A2 centre (31.21, 37.05) radius 0.45 clockwise from (31.21, 37.5) to (31.66, 37.05)
  arc A3 centre (30.71, 37.05) radius 0.45 clockwise from (30.26, 37.05) to (30.71, 37.5)
  arc A4 centre (30.71, 30.95) radius 0.45 clockwise from (30.71, 30.5) to (30.26, 30.95)
extrude "Extrude83" add sketch "PCB X Edge Locator Sketch (3)" blind 2 from offset 9.74
sketch "PCB Y Edge Locator Sketch" plane through (0, 0, 0) normal (0, 0, 1) x axis (1, 0, 0)
  line L1 (-25.45, -34.66) -> (-36.55, -34.66)
  line L2 (-25, -33.71) -> (-25, -34.21)
  line L3 (-36.55, -33.26) -> (-25.45, -33.26)
  line L4 (-37, -34.21) -> (-37, -33.71)
  arc A1 centre (-25.45, -34.21) radius 0.45 clockwise from (-25, -34.21) to (-25.45, -34.66)
  arc A2 centre (-25.45, -33.71) radius 0.45 clockwise from (-25.45, -33.26) to (-25, -33.71)
  arc A3 centre (-36.55, -33.71) radius 0.45 clockwise from (-37, -33.71) to (-36.55, -33.26)
  arc A4 centre (-36.55, -34.21) radius 0.45 clockwise from (-36.55, -34.66) to (-37, -34.21)
extrude "Extrude84" add sketch "PCB Y Edge Locator Sketch" blind 2 from offset 9.74
sketch "PCB Y Edge Locator Sketch (1)" plane through (0, 0, 0) normal (0, 0, 1) x axis (1, 0, 0)
  line L1 (36.55, -34.66) -> (25.45, -34.66)
  line L2 (37, -33.71) -> (37, -34.21)
  line L3 (25.45, -33.26) -> (36.55, -33.26)
  line L4 (25, -34.21) -> (25, -33.71)
  arc A1 centre (36.55, -34.21) radius 0.45 clockwise from (37, -34.21) to (36.55, -34.66)
  arc A2 centre (36.55, -33.71) radius 0.45 clockwise from (36.55, -33.26) to (37, -33.71)
  arc A3 centre (25.45, -33.71) radius 0.45 clockwise from (25, -33.71) to (25.45, -33.26)
  arc A4 centre (25.45, -34.21) radius 0.45 clockwise from (25.45, -34.66) to (25, -34.21)
extrude "Extrude85" add sketch "PCB Y Edge Locator Sketch (1)" blind 2 from offset 9.74
sketch "PCB Y Edge Locator Sketch (2)" plane through (0, 0, 0) normal (0, 0, 1) x axis (1, 0, 0)
  line L1 (-25.45, 47.26) -> (-36.55, 47.26)
  line L2 (-25, 48.21) -> (-25, 47.71)
  line L3 (-36.55, 48.66) -> (-25.45, 48.66)
  line L4 (-37, 47.71) -> (-37, 48.21)
  arc A1 centre (-25.45, 47.71) radius 0.45 clockwise from (-25, 47.71) to (-25.45, 47.26)
  arc A2 centre (-25.45, 48.21) radius 0.45 clockwise from (-25.45, 48.66) to (-25, 48.21)
  arc A3 centre (-36.55, 48.21) radius 0.45 clockwise from (-37, 48.21) to (-36.55, 48.66)
  arc A4 centre (-36.55, 47.71) radius 0.45 clockwise from (-36.55, 47.26) to (-37, 47.71)
extrude "Extrude86" add sketch "PCB Y Edge Locator Sketch (2)" blind 2 from offset 9.74
sketch "PCB Y Edge Locator Sketch (3)" plane through (0, 0, 0) normal (0, 0, 1) x axis (1, 0, 0)
  line L1 (36.55, 47.26) -> (25.45, 47.26)
  line L2 (37, 48.21) -> (37, 47.71)
  line L3 (25.45, 48.66) -> (36.55, 48.66)
  line L4 (25, 47.71) -> (25, 48.21)
  arc A1 centre (36.55, 47.71) radius 0.45 clockwise from (37, 47.71) to (36.55, 47.26)
  arc A2 centre (36.55, 48.21) radius 0.45 clockwise from (36.55, 48.66) to (37, 48.21)
  arc A3 centre (25.45, 48.21) radius 0.45 clockwise from (25, 48.21) to (25.45, 48.66)
  arc A4 centre (25.45, 47.71) radius 0.45 clockwise from (25.45, 47.26) to (25, 47.71)
extrude "Extrude87" add sketch "PCB Y Edge Locator Sketch (3)" blind 2 from offset 9.74
sketch "Front Screw Posts" plane through (0, 0, 0) normal (0, 0, 1) x axis (1, 0, 0)
  circle C1 centre (-33.4, -56) radius 2.8
  circle C2 centre (-33.4, 56) radius 2.8
  circle C3 centre (33.4, -56) radius 2.8
  circle C4 centre (33.4, 56) radius 2.8
extrude "Extrude88" add sketch "Front Screw Posts" blind 5 from offset 10
sketch "M2.5 Pilot Holes" plane through (0, 0, 0) normal (0, 0, 1) x axis (1, 0, 0)
  circle C1 centre (-33.4, -56) radius 1.05
  circle C2 centre (-33.4, 56) radius 1.05
  circle C3 centre (33.4, -56) radius 1.05
  circle C4 centre (33.4, 56) radius 1.05
extrude "Extrude89" cut sketch "M2.5 Pilot Holes" blind 5 from offset 10.5
sketch "Back Outer Housing" plane through (0, 0, 0) normal (0, 0, 1) x axis (1, 0, 0)
  line L1 (14, -75) -> (-14, -75)
  line L2 (39, 50) -> (39, -50)
  line L3 (-14, 75) -> (14, 75)
  line L4 (-39, -50) -> (-39, 50)
  arc A1 centre (14, -50) radius 25 clockwise from (39, -50) to (14, -75)
  arc A2 centre (14, 50) radius 25 clockwise from (14, 75) to (39, 50)
  arc A3 centre (-14, 50) radius 25 clockwise from (-39, 50) to (-14, 75)
  arc A4 centre (-14, -50) radius 25 clockwise from (-14, -75) to (-39, -50)
extrude "Extrude1" new body sketch "Back Outer Housing" blind 14.5 from offset 15
fillet "Fillet1" radius 10
sketch "Back Shell Concealed Seam Rabbet Sketch" plane through (0, 0, 0) normal (0, 0, 1) x axis (1, 0, 0)
  line L1 (14, -76) -> (-14, -76)
  line L2 (40, 50) -> (40, -50)
  line L3 (-14, 76) -> (14, 76)
  line L4 (-40, -50) -> (-40, 50)
  line L5 (14, -73.8) -> (-14, -73.8)
  line L6 (37.8, 50) -> (37.8, -50)
  line L7 (-14, 73.8) -> (14, 73.8)
  line L8 (-37.8, -50) -> (-37.8, 50)
  arc A1 centre (14, -50) radius 26 clockwise from (40, -50) to (14, -76)
  arc A2 centre (14, 50) radius 26 clockwise from (14, 76) to (40, 50)
  arc A3 centre (-14, 50) radius 26 clockwise from (-40, 50) to (-14, 76)
  arc A4 centre (-14, -50) radius 26 clockwise from (-14, -76) to (-40, -50)
  arc A5 centre (14, -50) radius 23.8 clockwise from (37.8, -50) to (14, -73.8)
  arc A6 centre (14, 50) radius 23.8 clockwise from (14, 73.8) to (37.8, 50)
  arc A7 centre (-14, 50) radius 23.8 clockwise from (-37.8, 50) to (-14, 73.8)
  arc A8 centre (-14, -50) radius 23.8 clockwise from (-14, -73.8) to (-37.8, -50)
extrude "Extrude2" cut sketch "Back Shell Concealed Seam Rabbet Sketch" blind 1.65 from offset 14.8
sketch "Back Cavity" plane through (0, 0, 0) normal (0, 0, 1) x axis (1, 0, 0)
  line L1 (14, -72.8) -> (-14, -72.8)
  line L2 (36.8, 50) -> (36.8, -50)
  line L3 (-14, 72.8) -> (14, 72.8)
  line L4 (-36.8, -50) -> (-36.8, 50)
  arc A1 centre (14, -50) radius 22.8 clockwise from (36.8, -50) to (14, -72.8)
  arc A2 centre (14, 50) radius 22.8 clockwise from (14, 72.8) to (36.8, 50)
  arc A3 centre (-14, 50) radius 22.8 clockwise from (-36.8, 50) to (-14, 72.8)
  arc A4 centre (-14, -50) radius 22.8 clockwise from (-14, -72.8) to (-36.8, -50)
extrude "Extrude3" new body sketch "Back Cavity" blind 12.5 from offset 14.8
fillet "Fillet2" radius 7.8
combine "Combine1"
sketch "Rear Palm Saddle Sketch" plane through (0, 0, 0) normal (0, 0, 1) x axis (1, 0, 0)
  line L1 (0.2, -47) -> (-0.2, -47)
  line L2 (22, 11.2) -> (22, -25.2)
  line L3 (-0.2, 33) -> (0.2, 33)
  line L4 (-22, -25.2) -> (-22, 11.2)
  arc A1 centre (0.2, -25.2) radius 21.8 clockwise from (22, -25.2) to (0.2, -47)
  arc A2 centre (0.2, 11.2) radius 21.8 clockwise from (0.2, 33) to (22, 11.2)
  arc A3 centre (-0.2, 11.2) radius 21.8 clockwise from (-22, 11.2) to (-0.2, 33)
  arc A4 centre (-0.2, -25.2) radius 21.8 clockwise from (-0.2, -47) to (-22, -25.2)
extrude "Extrude4" cut sketch "Rear Palm Saddle Sketch" blind -0.7 (= "-( 0.70 mm )") from offset 29.55
sketch "Sketch5" plane through (0, 0, 0) normal (0, 0, 1) x axis (1, 0, 0)
  line L1 (-20.9973, -49.4649) -> (-19.643, -54.535)
  line L2 (-19.7281, -49.4649) -> (-20.9973, -49.4649)
  line L3 (-19.2007, -51.7822) -> (-19.7281, -49.4649)
  curve K1 (-19.0679, -52.5002) -> (-19.2007, -51.7822)
  curve K2 (-18.9489, -53.2692) -> (-19.0679, -52.5002)
  curve K3 (-18.9352, -53.3611) -> (-18.9489, -53.2692)
  curve K4 (-18.9216, -53.2692) -> (-18.9352, -53.3611)
  curve K5 (-18.7923, -52.5002) -> (-18.9216, -53.2692)
  curve K6 (-18.646, -51.7822) -> (-18.7923, -52.5002)
  line L4 (-18.0846, -49.4649) -> (-18.646, -51.7822)
  line L5 (-16.9038, -49.4649) -> (-18.0846, -49.4649)
  line L6 (-16.3423, -51.7822) -> (-16.9038, -49.4649)
  curve K7 (-16.1977, -52.5002) -> (-16.3423, -51.7822)
  curve K8 (-16.0667, -53.2692) -> (-16.1977, -52.5002)
  curve K9 (-16.0531, -53.3543) -> (-16.0667, -53.2692)
  curve K10 (-16.0395, -53.2692) -> (-16.0531, -53.3543)
  curve K11 (-15.9221, -52.5002) -> (-16.0395, -53.2692)
  curve K12 (-15.7877, -51.7822) -> (-15.9221, -52.5002)
  line L7 (-15.2603, -49.4649) -> (-15.7877, -51.7822)
  line L8 (-13.9876, -49.4649) -> (-15.2603, -49.4649)
  line L9 (-15.3453, -54.535) -> (-13.9876, -49.4649)
  line L10 (-16.6554, -54.535) -> (-15.3453, -54.535)
  line L11 (-17.2713, -52.1191) -> (-16.6554, -54.535)
  curve K13 (-17.4652, -51.1084) -> (-17.2713, -52.1191)
  curve K14 (-17.4993, -50.8805) -> (-17.4652, -51.1084)
  curve K15 (-17.5265, -51.0948) -> (-17.4993, -50.8805)
  curve K16 (-17.7137, -52.1191) -> (-17.5265, -51.0948)
  line L12 (-18.333, -54.535) -> (-17.7137, -52.1191)
  line L13 (-19.643, -54.535) -> (-18.333, -54.535)
  line L14 (-12.7116, -49.4649) -> (-14.4164, -54.535)
  line L15 (-11.1804, -49.4649) -> (-12.7116, -49.4649)
  line L16 (-9.428, -54.535) -> (-11.1804, -49.4649)
  line L17 (-10.7176, -54.535) -> (-9.428, -54.535)
  line L18 (-11.0749, -53.4257) -> (-10.7176, -54.535)
  line L19 (-12.7967, -53.4257) -> (-11.0749, -53.4257)
  line L20 (-13.1404, -54.535) -> (-12.7967, -53.4257)
  line L21 (-14.4164, -54.535) -> (-13.1404, -54.535)
  line L22 (-11.4526, -52.2484) -> (-11.3608, -52.541)
  curve K17 (-11.7725, -51.1152) -> (-11.4526, -52.2484)
  curve K18 (-11.9596, -50.3734) -> (-11.7725, -51.1152)
  curve K19 (-12.1332, -51.1187) -> (-11.9596, -50.3734)
  curve K20 (-12.4292, -52.2484) -> (-12.1332, -51.1187)
  line L23 (-12.5211, -52.541) -> (-12.4292, -52.2484)
  line L24 (-11.3608, -52.541) -> (-12.5211, -52.541)
  line L25 (-9.0718, -49.4649) -> (-9.0718, -54.535)
  line L26 (-7.9199, -49.4649) -> (-9.0718, -49.4649)
  line L27 (-7.9199, -53.5902) -> (-7.9199, -49.4649)
  line L28 (-5.7798, -53.5902) -> (-7.9199, -53.5902)
  line L29 (-5.7798, -54.535) -> (-5.7798, -53.5902)
  line L30 (-9.0718, -54.535) -> (-5.7798, -54.535)
  line L31 (-5.3516, -49.4649) -> (-5.3516, -54.535)
  line L32 (-4.2015, -49.4649) -> (-5.3516, -49.4649)
  line L33 (-4.2015, -50.7512) -> (-4.2015, -49.4649)
  line L34 (-4.2219, -51.9557) -> (-4.2015, -50.7512)
  curve K21 (-4.198, -51.9149) -> (-4.2219, -51.9557)
  curve K22 (-3.8731, -51.4232) -> (-4.198, -51.9149)
  curve K23 (-3.4494, -50.8702) -> (-3.8731, -51.4232)
  line L35 (-2.2891, -49.4649) -> (-3.4494, -50.8702)
  line L36 (-0.8974, -49.4649) -> (-2.2891, -49.4649)
  line L37 (-2.7519, -51.6563) -> (-0.8974, -49.4649)
  line L38 (-0.8293, -54.535) -> (-2.7519, -51.6563)
  line L39 (-2.187, -54.535) -> (-0.8293, -54.535)
  line L40 (-3.5447, -52.4117) -> (-2.187, -54.535)
  line L41 (-4.2015, -53.1467) -> (-3.5447, -52.4117)
  line L42 (-4.2015, -54.535) -> (-4.2015, -53.1467)
  line L43 (-5.3516, -54.535) -> (-4.2015, -54.535)
  line L44 (0.6822, -54.535) -> (0.6822, -49.4649)
  line L45 (-0.4697, -54.535) -> (0.6822, -54.535)
  line L46 (-0.4697, -49.4649) -> (-0.4697, -54.535)
  line L47 (0.6822, -49.4649) -> (-0.4697, -49.4649)
  line L48 (1.2895, -49.4649) -> (1.2895, -54.535)
  line L49 (4.7712, -49.4649) -> (1.2895, -49.4649)
  line L50 (4.7712, -50.4097) -> (4.7712, -49.4649)
  line L51 (2.4414, -50.4097) -> (4.7712, -50.4097)
  line L52 (2.4414, -51.5108) -> (2.4414, -50.4097)
  line L53 (4.5879, -51.5108) -> (2.4414, -51.5108)
  line L54 (4.5879, -52.4367) -> (4.5879, -51.5108)
  line L55 (2.4414, -52.4367) -> (4.5879, -52.4367)
  line L56 (2.4414, -53.5902) -> (2.4414, -52.4367)
  line L57 (4.7711, -53.5902) -> (2.4414, -53.5902)
  line L58 (4.7711, -54.535) -> (4.7711, -53.5902)
  line L59 (1.2895, -54.535) -> (4.7711, -54.535)
  curve K24 (8.2883, -54.2889) -> (9.4502, -54.6031)
  curve K25 (7.4839, -53.3912) -> (8.2883, -54.2889)
  curve K26 (7.19, -52.0034) -> (7.4839, -53.3912)
  curve K27 (7.4839, -50.6119) -> (7.19, -52.0034)
  curve K28 (8.2883, -49.7126) -> (7.4839, -50.6119)
  curve K29 (9.4502, -49.3969) -> (8.2883, -49.7126)
  curve K30 (10.6105, -49.7126) -> (9.4502, -49.3969)
  curve K31 (11.4116, -50.6119) -> (10.6105, -49.7126)
  curve K32 (11.7039, -52.0034) -> (11.4116, -50.6119)
  curve K33 (11.4116, -53.3913) -> (11.7039, -52.0034)
  curve K34 (10.6105, -54.2889) -> (11.4116, -53.3913)
  curve K35 (9.4502, -54.6031) -> (10.6105, -54.2889)
  curve K36 (10.2599, -53.7554) -> (9.4502, -53.9826)
  curve K37 (10.8335, -53.0855) -> (10.2599, -53.7554)
  curve K38 (11.0461, -52.0034) -> (10.8335, -53.0855)
  curve K39 (10.8335, -50.9145) -> (11.0461, -52.0034)
  curve K40 (10.2599, -50.2445) -> (10.8335, -50.9145)
  curve K41 (9.4502, -50.0173) -> (10.2599, -50.2445)
  curve K42 (8.6358, -50.2462) -> (9.4502, -50.0173)
  curve K43 (8.0605, -50.9177) -> (8.6358, -50.2462)
  curve K44 (7.8478, -52.0034) -> (8.0605, -50.9177)
  curve K45 (8.0605, -53.0839) -> (7.8478, -52.0034)
  curve K46 (8.6358, -53.7537) -> (8.0605, -53.0839)
  curve K47 (9.4502, -53.9826) -> (8.6358, -53.7537)
  line L60 (12.6604, -49.4649) -> (12.6604, -54.535)
  line L61 (13.4498, -49.4649) -> (12.6604, -49.4649)
  line L62 (15.4812, -52.6635) -> (13.4498, -49.4649)
  curve K48 (15.682, -52.9919) -> (15.4812, -52.6635)
  curve K49 (15.9304, -53.4427) -> (15.682, -52.9919)
  curve K50 (16.0801, -53.732) -> (15.9304, -53.4427)
  curve K51 (16.0597, -53.4189) -> (16.0801, -53.732)
  curve K52 (16.0393, -52.9187) -> (16.0597, -53.4189)
  curve K53 (16.0359, -52.5308) -> (16.0393, -52.9187)
  line L63 (16.0359, -49.4649) -> (16.0359, -52.5308)
  line L64 (16.7096, -49.4649) -> (16.0359, -49.4649)
  line L65 (16.7096, -54.535) -> (16.7096, -49.4649)
  line L66 (15.9168, -54.535) -> (16.7096, -54.535)
  line L67 (14.1031, -51.6869) -> (15.9168, -54.535)
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extrude "Extrude5" cut sketch "Sketch5" blind -0.4 (= "-( 0.40 mm )") from offset 29.55
sketch "Designed in Los Angeles Rear Tagline" plane through (0, 0, 0) normal (0, 0, 1) x axis (1, 0, 0)
  dimension "d328" = 1.6
extrude "Extrude6" cut sketch "Designed in Los Angeles Rear Tagline" blind -0.3 (= "-( 0.30 mm )") from offset 29.55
